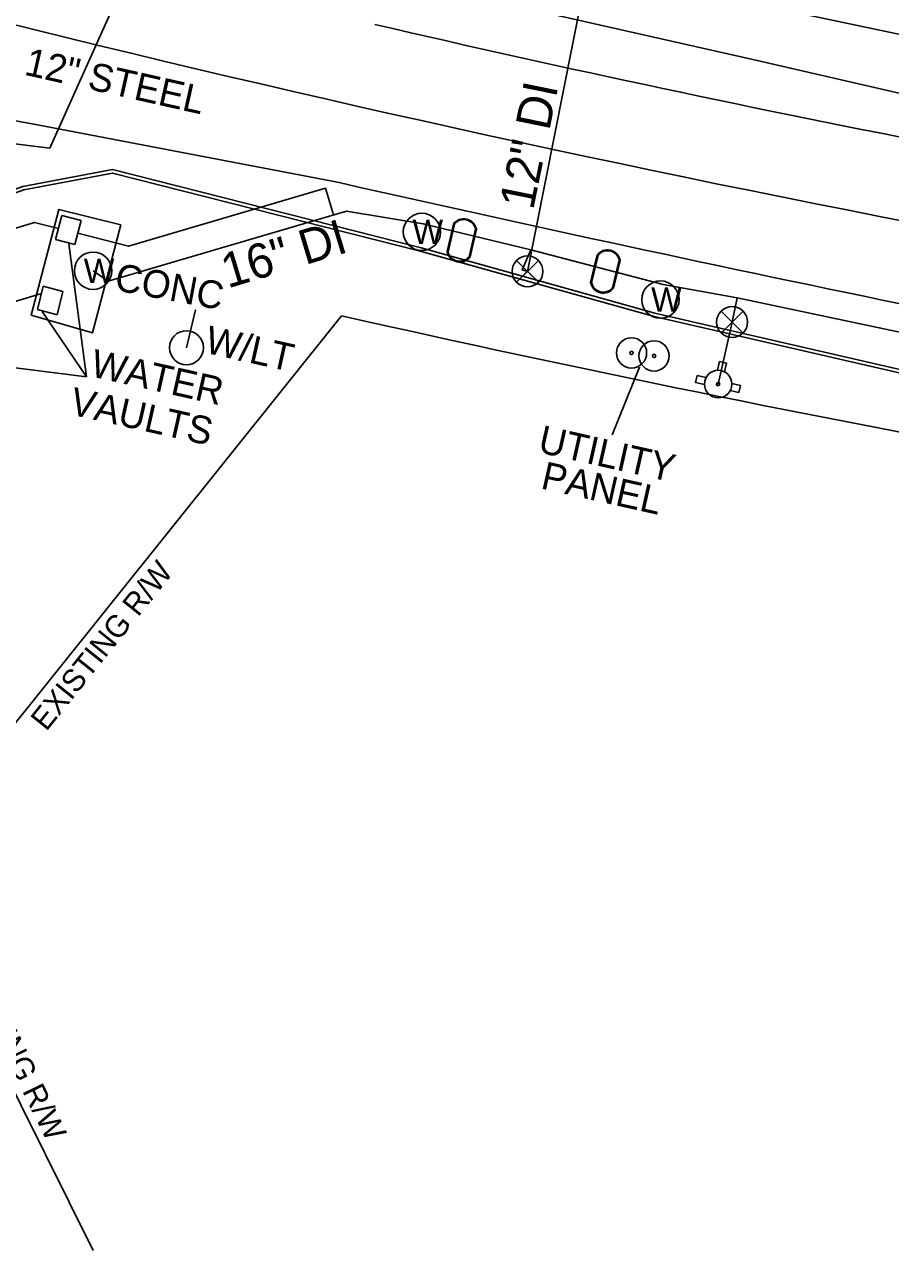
# Model space of a CAD drawing. Extents: x 1784037 to 1786391, y 840555 to 842045.
# Drawn here: x 1785744.6 to 1785869.5, y 841232.7 to 841409.5 of the extents above; entities that cross this region are included whole.
import ezdxf

# ---------------------------------------------------------------- set-up
doc = ezdxf.new("R2010")
doc.units = 0
for name, color, linetype in [('Exist Horizontal Alignment', 7, 'Continuous'), ('Exist Other Culture Area Outline', 7, 'Continuous'), ('Exist Other Culture Area Outline Text', 7, 'Continuous'), ('Exist Right of Way Line', 7, 'Continuous'), ('Exist Right of Way Line Text', 7, 'Continuous'), ('Exist Roads EOP', 7, 'Continuous'), ('Exist Structure Minor Pipes RCP 12 Inch Text', 7, 'Continuous'), ('Exist Utilities Other Located Object CELL', 7, 'Continuous'), ('Exist Utilities Other Located Object Leader', 7, 'Continuous'), ('Exist Utilities Other Located Object Text', 7, 'Continuous'), ('Exist Utilities Power Pole CELL', 7, 'Continuous'), ('Exist Utilities Power Pole Text', 7, 'Continuous'), ('Exist Utilities Telephone UG Cable SUE LOS B', 7, 'Continuous'), ('Exist Utilities Telephone UG Conduit SUE LOS B', 7, 'Continuous'), ('Exist Utilities TV UG Cable SUE LOS B', 7, 'Continuous'), ('Exist Utilities TV UG FO Cable SUE LOS B', 7, 'Continuous'), ('Exist Utilities Water Fire Hydrant CELL', 7, 'Continuous'), ('Exist Utilities Water Manhole CELL', 7, 'Continuous'), ('Exist Utilities Water Meter CELL', 7, 'Continuous'), ('Exist Utilities Water UG Line SUE LOS B', 7, 'Continuous'), ('Exist Utilities Water UG Line SUE LOS B Text', 7, 'Continuous'), ('Exist Utilities Water UG Line SUE LOS C', 7, 'Continuous'), ('Exist Utilities Water Valve CELL', 7, 'Continuous'), ('Exist Utilities Water Valve Leader', 7, 'Continuous'), ('Exist Utilities Water Valve Text', 7, 'Continuous')]:
    doc.layers.add(name, color=color, linetype=linetype)

msp = doc.modelspace()

# ---------------------------------------------------------------- linework, layer by layer
at = {"layer": 'Exist Horizontal Alignment'}
msp.add_arc((1786356.43, 843884.61), 2550, 255.06834, 261.97903, dxfattribs=at)
at = {"layer": 'Exist Other Culture Area Outline'}
msp.add_lwpolyline([(1785745.55, 841367.59), (1785749.54, 841382.83), (1785758.45, 841380.6), (1785754.37, 841365.02), (1785745.55, 841367.59)], dxfattribs=at)
at = {"layer": 'Exist Right of Way Line'}
for p, q in [((1785726.82, 841288.27), (1785790.29, 841367.49)), ((1785754.5, 841232.67), (1785726.82, 841288.27))]:
    msp.add_line(p, q, dxfattribs=at)
for radius, start in [(2520, 257.63448), (2580, 257.32422)]:
    msp.add_arc((1786356.43, 843884.61), radius, start, 261.97903, dxfattribs=at)
at = {"layer": 'Exist Roads EOP'}
msp.add_lwpolyline([(1785727.59, 841396.53), (1785735.34, 841397.07), (1785746.43, 841395.06), (1785789.97, 841386.7)], dxfattribs=at)
for centre, major_axis, ratio, start_param, end_param in [((1786328.36, 843691.04), (2278.89, 564.29), 0.997479, 4.241075, 4.277341), ((1786741.88, 845574.01), (3835.96, 1938.36), 0.998535, 4.021687, 4.041595)]:
    msp.add_ellipse(centre, major_axis=major_axis, ratio=ratio, start_param=start_param, end_param=end_param, dxfattribs=at)
at = {"layer": 'Exist Utilities Other Located Object CELL'}
for centre, radius in [((1785832.15, 841362.14), 2.18), ((1785835.4, 841361.71), 2.18), ((1785832.15, 841362.14), 0.24), ((1785835.4, 841361.71), 0.24)]:
    msp.add_circle(centre, radius, dxfattribs=at)
at = {"layer": 'Exist Utilities Other Located Object Leader'}
msp.add_line((1785833.32, 841360.06), (1785829.35, 841350.31), dxfattribs=at)
at = {"layer": 'Exist Utilities Power Pole CELL'}
for q in [(1785769.23, 841368.36), (1785767.94, 841362.89)]:
    msp.add_line((1785767.94, 841362.89), q, dxfattribs=at)
msp.add_circle((1785767.94, 841362.89), 2.45, dxfattribs=at)
at = {"layer": 'Exist Utilities Telephone UG Cable SUE LOS B'}
msp.add_lwpolyline([(1785644.61, 841325.43), (1785645.69, 841326.11), (1785650.96, 841329.37), (1785683.11, 841351.09), (1785686.94, 841354.09), (1785688.01, 841356.42), (1785690.32, 841375.38), (1785694.46, 841382.13), (1785715.72, 841391.76), (1785740.77, 841392.59), (1785748.22, 841391.67), (1785751.5, 841399), (1785766.73, 841432.92)], dxfattribs=at)
at = {"layer": 'Exist Utilities Telephone UG Conduit SUE LOS B'}
for points in [[(1785711.37, 841439.59), (1785726.7, 841434.64), (1785787.55, 841418.28), (1785790.36, 841417.86), (1785849.65, 841404.45), (1785889.76, 841395.25), (1785954.26, 841383.13), (1785994.03, 841378.2)], [(1785850.79, 841412.3), (1785898.1, 841402.35), (1785950.25, 841392.73), (1785995.63, 841386.66)]]:
    msp.add_lwpolyline(points, dxfattribs=at)
at = {"layer": 'Exist Utilities TV UG Cable SUE LOS B'}
msp.add_lwpolyline([(1785709.79, 841338.02), (1785710.13, 841347.55), (1785715.06, 841362.93), (1785725.15, 841379.22), (1785744.35, 841386.13), (1785757.26, 841388.59), (1785801.79, 841377.32), (1785835.53, 841367.86), (1785883.42, 841356.87), (1785888.55, 841352.97), (1785887.68, 841345.12)], dxfattribs=at)
at = {"layer": 'Exist Utilities TV UG FO Cable SUE LOS B'}
msp.add_lwpolyline([(1785709.79, 841338.02), (1785710.62, 841347.46), (1785715.52, 841362.72), (1785725.48, 841378.8), (1785744.49, 841385.64), (1785757.25, 841388.08), (1785801.66, 841376.84), (1785835.4, 841367.37), (1785883.31, 841356.39), (1785883.61, 841355.79), (1785886.68, 841352.59), (1785887.68, 841345.12)], dxfattribs=at)
at = {"layer": 'Exist Utilities Water Fire Hydrant CELL'}
msp.add_line((1785844.64, 841357.65), (1785844.64, 841357.65), dxfattribs=at)
for points in [[(1785845.57, 841359.4), (1785845.85, 841360.65), (1785844.86, 841360.88), (1785844.57, 841359.63)], [(1785842.89, 841358.58), (1785841.63, 841358.87), (1785841.4, 841357.87), (1785842.68, 841357.58)], [(1785846.62, 841357.72), (1785847.87, 841357.43), (1785847.64, 841356.43), (1785846.36, 841356.73)]]:
    msp.add_lwpolyline(points, dxfattribs=at)
for radius in [1.98, 0.243]:
    msp.add_circle((1785844.64, 841357.65), radius, dxfattribs=at)
at = {"layer": 'Exist Utilities Water Manhole CELL'}
for p, q in [((1785801.9, 841379.59), (1785801.9, 841379.59)), ((1785754.47, 841373.98), (1785754.47, 841373.98)), ((1785836.32, 841369.83), (1785836.32, 841369.83))]:
    msp.add_line(p, q, dxfattribs=at)
for centre in [(1785801.9, 841379.6), (1785754.47, 841373.99), (1785836.32, 841369.83)]:
    msp.add_circle(centre, 2.69, dxfattribs=at)
at = {"layer": 'Exist Utilities Water Meter CELL'}
for p, q in [((1785807.66, 841378.36), (1785807.66, 841378.36)), ((1785828.38, 841373.89), (1785828.38, 841373.89))]:
    msp.add_line(p, q, dxfattribs=at)
for points in [[(1785805.55, 841376.75), (1785806.45, 841380.73)], [(1785805.69, 841376.72), (1785806.59, 841380.7)], [(1785809.64, 841380.01), (1785808.73, 841376.01)], [(1785809.77, 841379.97), (1785808.86, 841375.98)], [(1785826.25, 841372.3), (1785827.2, 841376.27)], [(1785826.38, 841372.27), (1785827.34, 841376.23)], [(1785830.37, 841375.5), (1785829.42, 841371.52)], [(1785830.51, 841375.47), (1785829.55, 841371.48)]]:
    msp.add_lwpolyline(points, dxfattribs=at)
for centre, radius, start, end in [((1785807.95, 841379.62), 1.86, 10.8842, 143.5443), ((1785807.95, 841379.64), 1.73, 12.3631, 142.1087), ((1785807.38, 841377.09), 1.86, 190.4139, 323.2153), ((1785807.38, 841377.1), 1.73, 192.5368, 321.0182), ((1785828.68, 841375.14), 1.86, 10.1434, 142.8035), ((1785828.68, 841375.16), 1.73, 11.6223, 141.3679), ((1785828.08, 841372.62), 1.86, 189.6731, 322.4745), ((1785828.08, 841372.63), 1.73, 191.796, 320.2774)]:
    msp.add_arc(centre, radius, start, end, dxfattribs=at)
at = {"layer": 'Exist Utilities Water UG Line SUE LOS B'}
for points in [[(1785815.12, 841481.05), (1785815.26, 841476.19), (1785814.67, 841473.89), (1785812.1, 841461.47), (1785822.06, 841430.92), (1785825.71, 841421.3), (1785826.16, 841419.45), (1785817.14, 841373.9), (1785816.35, 841374.12), (1785817.64, 841376.99)], [(1785754.47, 841373.98), (1785756.64, 841372.49), (1785791.04, 841382.6), (1785802.09, 841380.77), (1785817.64, 841376.99), (1785836.69, 841372.02), (1785847.4, 841370.08), (1785880.63, 841363.05), (1785956.71, 841349.33), (1785994.35, 841344.56)], [(1785650.58, 841326.98), (1785663.18, 841332.68), (1785692.85, 841347.81), (1785712.85, 841358.89), (1785728.44, 841365.09), (1785747.02, 841370.69)], [(1785847.4, 841370.08), (1785846.66, 841366.59), (1785844.64, 841357.65)]]:
    msp.add_lwpolyline(points, dxfattribs=at)
at = {"layer": 'Exist Utilities Water UG Line SUE LOS C'}
for points in [[(1785752.26, 841379.41), (1785759.57, 841377.53), (1785787.99, 841385.89), (1785789.13, 841382.04)], [(1785731.31, 841365.96), (1785728.43, 841375.66), (1785746.03, 841380.96), (1785749.47, 841380.07)]]:
    msp.add_lwpolyline(points, dxfattribs=at)
at = {"layer": 'Exist Utilities Water Valve CELL'}
for p, q in [((1785749.06, 841378.5), (1785749.95, 841381.96)), ((1785749.95, 841381.96), (1785752.73, 841381.22)), ((1785752.73, 841381.22), (1785751.84, 841377.76)), ((1785751.84, 841377.76), (1785749.06, 841378.5)), ((1785746.43, 841368.42), (1785747.29, 841371.77)), ((1785747.29, 841371.77), (1785750.12, 841370.99)), ((1785750.12, 841370.99), (1785749.27, 841367.64)), ((1785749.27, 841367.64), (1785746.43, 841368.42))]:
    msp.add_line(p, q, dxfattribs=at)
for points in [[(1785818.71, 841375.48), (1785815.56, 841372.33), (1785817.14, 841373.9), (1785818.71, 841372.33), (1785815.56, 841375.48)], [(1785848.23, 841368.16), (1785845.08, 841365.01), (1785846.66, 841366.59), (1785848.23, 841365.01), (1785845.08, 841368.16)]]:
    msp.add_lwpolyline(points, dxfattribs=at)
for centre in [(1785817.14, 841373.9), (1785846.66, 841366.59)]:
    msp.add_circle(centre, 2.23, dxfattribs=at)
at = {"layer": 'Exist Utilities Water Valve Leader'}
for p in [(1785747.14, 841368.1), (1785711.69, 841363.93)]:
    msp.add_line(p, (1785753.53, 841358.67), dxfattribs=at)
msp.add_lwpolyline([(1785750.96, 841377.88), (1785753.53, 841358.67)], dxfattribs=at)

# ---------------------------------------------------------------- texts
at = {"layer": 'Exist Other Culture Area Outline Text'}
msp.add_text('CONC', height=4, rotation=349.4059, dxfattribs=at).set_placement((1785757.4, 841371.21))
at = {"layer": 'Exist Right of Way Line Text'}
for rotation, p in [(51.3013, (1785747.72, 841307.45)), (295.9515, (1785734.95, 841274.73))]:
    msp.add_text('EXISTING R/W', height=3.2, rotation=rotation, dxfattribs=at).set_placement(p)
at = {"layer": 'Exist Structure Minor Pipes RCP 12 Inch Text'}
msp.add_text('12" STEEL', height=4, rotation=347.3599, dxfattribs=at).set_placement((1785744.4, 841402.29))
at = {"layer": 'Exist Utilities Other Located Object Text'}
for s, p in [('UTILITY', (1785818.49, 841347.84)), ('PANEL', (1785818.9, 841342.61))]:
    msp.add_text(s, height=4, rotation=347.3599, dxfattribs=at).set_placement(p)
at = {"layer": 'Exist Utilities Power Pole Text'}
msp.add_text('W/LT', height=4, rotation=347.3599, dxfattribs=at).set_placement((1785770.42, 841362.2))
at = {"layer": 'Exist Utilities Water Manhole CELL'}
for p in [(1785800.55, 841377.84), (1785753.12, 841372.23), (1785834.97, 841368.08)]:
    msp.add_text('W', height=3.5, dxfattribs=at).set_placement(p)
at = {"layer": 'Exist Utilities Water UG Line SUE LOS B Text'}
for s, rotation, p in [('12" DI', 78.5034, (1785817.95, 841382.64)), ('16" DI', 16.8368, (1785773.89, 841371.42))]:
    msp.add_text(s, height=5, rotation=rotation, dxfattribs=at).set_placement(p)
at = {"layer": 'Exist Utilities Water Valve Text'}
for s, p in [('WATER', (1785753.9, 841358.8)), ('VAULTS', (1785750.9, 841353.32))]:
    msp.add_text(s, height=4, rotation=347.3599, dxfattribs=at).set_placement(p)

doc.saveas('drawing.dxf')
